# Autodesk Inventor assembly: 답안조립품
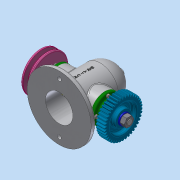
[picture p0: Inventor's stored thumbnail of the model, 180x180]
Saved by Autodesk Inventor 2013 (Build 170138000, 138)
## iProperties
Created: 2019-11
Part Number: 답안조립품
Document SubType Name: Assembly
Designer: Administrator
Author: Administrator
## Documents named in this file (14)
- C:\Users\Administrator\Desktop\491104V1009\답안조립품.iam
- C:\Users\Administrator\Desktop\491104V1009\1-본체.ipt
- C:\Users\Administrator\Desktop\491104V1009\커버.ipt
- C:\Users\Administrator\Desktop\491104V1009\베어링 6203.ipt
- C:\Users\Administrator\Desktop\491104V1009\오일 실 26 38 8.ipt
- C:\Users\Administrator\Desktop\491104V1009\축.ipt
- C:\Users\Administrator\Desktop\491104V1009\키 5x5x12.ipt
- C:\Users\Administrator\Desktop\491104V1009\부시.ipt
- C:\Users\Administrator\Desktop\491104V1009\V-벨트풀리.ipt
- V-벨트풀리.ipt
- C:\Users\Administrator\Desktop\491104V1009\스퍼기어.ipt
- C:\Users\Administrator\Desktop\491104V1009\와셔 12x24.ipt
- C:\Users\Administrator\Desktop\491104V1009\너트 M12x1.25.ipt
- C:\Users\Administrator\Desktop\491104V1009\볼트 M4.ipt
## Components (2 placed, 2 different names)
1. 1-본체:1 — 각도:4, 각도:5, 각도:6, 각도:7, 각도:8, 각도:9
2. V-벨트풀리:1 — 각도:2
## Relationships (7: Angle 7)
- 각도:2 [Angle]: V-벨트풀리:1
- 각도:4 [Angle]: 1-본체:1
- 각도:5 [Angle]: 1-본체:1
- 각도:6 [Angle]: 1-본체:1
- 각도:7 [Angle]: 1-본체:1
- 각도:8 [Angle]: 1-본체:1
- 각도:9 [Angle]: 1-본체:1
